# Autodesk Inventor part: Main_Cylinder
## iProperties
Company: Autodesk, Inc.
Created: 2004-06
Part Number: Main_Cylinder
Document SubType Name: Modeling
Designer: Autodesk
Manufacturer: Standard
Standards Organization: Custom
Density: 1 g/cm^3
Author: Autodesk, Inc.
Subject: Autodesk Inventor
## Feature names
1. Extrusion1
2. Mirror1
3. Extrusion2
4. Extrusion3
